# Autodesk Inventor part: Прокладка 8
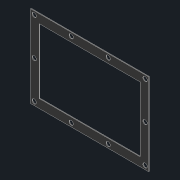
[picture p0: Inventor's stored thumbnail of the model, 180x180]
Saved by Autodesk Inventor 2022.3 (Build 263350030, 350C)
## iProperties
Created: 2022-08
Part Number: Прокладка 8
Material: Резина
Document SubType Name: Modeling
Designer: Карташов
Density: 0.93 g/cm^3
Appearance: Резина — черная
Author: Карташов
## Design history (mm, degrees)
sketch "Эскиз1"
  geometry: L1 (-85, -60)-(-85, 60) reference; L2 (85, -60)-(-85, -60) reference; L3 (85, 60)-(85, -60) reference; L4 (-85, 60)-(85, 60) reference; L5 (70, -45)-(70, 45) reference; L6 (-70, -45)-(70, -45) reference; L7 (-70, 45)-(-70, -45) reference; L8 (70, 45)-(-70, 45) reference; L9 (82, -57)-(82, 57) reference; L10 (82, 57)-(-82, 57) reference; L11 (-82, 57)-(-82, -57) reference; L12 (-82, -57)-(82, -57) reference; C1 r 3 at (-25.665, -52) reference; C2 r 3 at (-77, -52) reference; C3 r 5 at (25.665, -52) reference; C4 r 5 at (77, -52) reference; C5 r 5 at (25.665, 52) reference; C6 r 5 at (77, 52) reference; C7 r 5 at (77, 0) reference; C8 r 5 at (-25.665, -52) reference; C9 r 5 at (-77, -52) reference; C10 r 5 at (-25.665, 52) reference; C11 r 5 at (-77, 52) reference; C12 r 5 at (-77, 0) reference; C13 r 3 at (-77, 0) reference; C14 r 3 at (-77, 52) reference; C15 r 3 at (-25.665, 52) reference; C16 r 3 at (25.665, 52) reference; C17 r 3 at (77, 52) reference; C18 r 3 at (77, 0) reference; C19 r 3 at (77, -52) reference; C20 r 3 at (25.665, -52) reference; 1 further point
extrude "Выдавливание1" new body sketch "Эскиз1" distance "d0" = 1; taper "d1" = 0 deg
node "Твердое тело1"
node "Ссылка1"
node "Ссылка2"
node "Ссылка3"
node "Ссылка4"
node "Ссылка5"
node "Ссылка6"
node "Ссылка7"
node "Ссылка8"
node "Ссылка9"
node "Ссылка10"
node "Ссылка11"
node "Ссылка12"
node "Ссылка13"
node "Ссылка14"
node "Ссылка15"
